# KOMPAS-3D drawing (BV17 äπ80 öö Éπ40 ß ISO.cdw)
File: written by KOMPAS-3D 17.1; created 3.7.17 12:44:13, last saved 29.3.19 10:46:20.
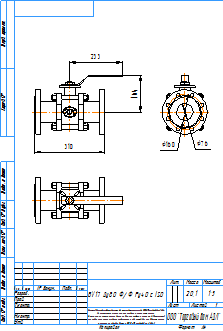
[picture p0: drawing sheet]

Sheet 1: A4, portrait

Title block, sheet 1: name: BV17 Ду80 Ф/Ф Ру40 с ISO; material: Сталь 20  ГОСТ 1050-88; mass: 20,1; sheets: 1; sheet format: A4; stored path: C:\Users\kka\KOMPAS_Work\!Trash\СС02 СС03 ФФ Смотровые стекла\СС01.cdw

Views: Спереди 1, Проекционный вид 2, Проекционный вид 3
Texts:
  Klimkovich
  ADL
  Рама для чертежей
  Лит-Масса-Масштаб
  Материал-Предприятие
  Масштаб
  Изм.
  Лист
  № докум.
  Подп.
  Дата
  Лит.
  Разраб.
  Пров.
  Т.контр.
  Листов
  Внимание! Данный продукт является объектом авторского права ООО «Торговый Дом АДЛ».
  Запрещается изменение, копирование, распространение
  (в том числе путем копирования на другие сайты и ресурсы в Интернете)
  или любое иное использование информации и объектов без предварительного
  согласия правообладателя (ООО «Торговый Дом АДЛ»).
  Н.контр.
  Утв.
  ООО "Торговый дом АДЛ"
  Изменение
  Номер документа
  Подпись
  Обозначение документа
  Наименование изделия
  Масса изделия по ГОСТ 2.109-73
  Порядковый номер листа
  Общее количество листов в документе
  Характер работы, выполненной лицом, подписавшим документ
  Наименование или индекс предприятия, выпускающего документ
  Инв. № подл.
  Подп. и дата
  Взам. инв. №
  Инв. № дубл.
  Инвентарный номер подлинника по ГОСТ 2.501-68
  Подпись принявшего подлинник в отдел технической документации
  Инвентарный номер подлинника, взамен которого выпущен данный подлинник
  Инвентарный номер дубликата по ГОСТ 2.502-68
  Подпись принявшего дубликат в отдел технической документации
  Справ. №
  Перв. примен.
  Обозначение документа, взамен или на основании которого выпущен данный документ
  Обозначение документа, в котором впервые записан данный документ
  Подпись лица, копировавшего чертеж
  Обозначение формата листа
  !Рама для чертежа
Dimensions and other numbers on the sheet: 233; 310; 164; 160; 76; 1:5; 1; 20,1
